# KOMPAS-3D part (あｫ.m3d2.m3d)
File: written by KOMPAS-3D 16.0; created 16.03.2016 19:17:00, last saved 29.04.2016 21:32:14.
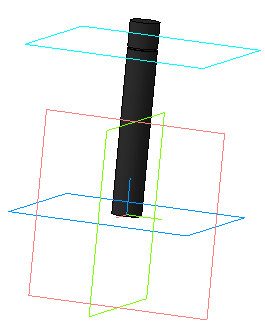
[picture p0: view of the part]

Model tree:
1. Эскиз:1
2. Операция выдавливания:1
     Расстояние 1 = 52
3. Смещенная плоскость:1
     Расстояние = 45
4. Эскиз:2
5. Вырезать элемент выдавливания:1
     Расстояние 1 = 0.5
